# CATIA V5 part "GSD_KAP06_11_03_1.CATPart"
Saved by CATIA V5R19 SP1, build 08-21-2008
Part number: GSD_BLEND_04
Definition: Beispielmodell für die Funktion Übergang / Blend - Automatische Verbindung.
Description: CATIA V5 Flächenmodellierung  Copyright (c) 2009 Maik Hertha IT Consultants
Bounding box of the stored display mesh (mm): x -164.511 to 102.98, y -20 to 224.611, z -30.362 to 44.999
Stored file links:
  \GSD_BUCH_UEBUNG\GSD_KAP06_11_03_1.CATPart
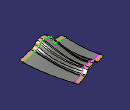
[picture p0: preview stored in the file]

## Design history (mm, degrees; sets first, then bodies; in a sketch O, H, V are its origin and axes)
AxisSystem1: origin (0, 0, 0), X (1, 0, 0), Y (0, 1, 0), Z (0, 0, 1)
Set1
  Sketch1 on ZX plane of AxisSystem1, origin (0, 0, 0), H (0, 0, 1), V (1, 0, 0)
    line L1 (-7.7811, 102.9804) -> (10.5771, 41.6998)
    arc A1 centre (44.1049, 51.744) radius 35 from (10.5771, 41.6998) to (24.809, 22.5435) ccw
    arc A2 centre (0, -15) radius 45 from (24.809, 22.5435) to (37.9923, 9.116) cw
    point P5 (0, -15)
    arc A3 centre (0, -15) radius 45 from (33.7014, -44.8197) to (4.0909, -59.8137) cw
    point P7 (0, -15)
    line L2 (-5, -69.7723) -> (-5, -121.1063)
    construction line L3 (70.2481, 0) -> (-64.8444, 0)
    point P8 (70.2481, 0)
    construction line L4 (0, 45.8622) -> (0, -41.9018)
    point P10 (0, 45.8622)
    curve C1
    arc A4 centre (5, -69.7723) radius 10 from (4.0909, -59.8137) to (-5, -69.7723) ccw
    arc A5 centre (0, -15) radius 45 from (37.9923, 9.116) to (43.6257, -3.9639) cw
    arc A6 centre (0, -15) radius 45 from (41.4452, -32.5298) to (33.7014, -44.8197) cw
    arc A7 centre (0, -15) radius 45 from (43.6257, -3.9639) to (41.4452, -32.5298) cw
    radius A3 = 45
    distance L4 L2 = 5
    distance P5 L3 = 15
    radius A4 = 10
    radius A1 = 35
    tangency: A1 L1, A2 A1, A3 A2, A4 L2, A4 A3
    vertical: L2 V, L4 V
    coincidence: P7 P5, P8 H, P10 V, P5 L4, A2 A5, A5 A6, A5 A7
    horizontal: L3 H
  Sketch2 on XY plane of AxisSystem1, origin (0, 0, 0), H (1, 0, 0), V (0, 1, 0)
    spline S1 through (63.5198, 0.6594) (52.4947, 108.5036) (27.7222, 201.6743)
    construction line L1 (63.5198, -33.9776) -> (63.5198, 23.4257)
    curve C1
    vertical: L1 V
  Plane1: type Normal, Curve Sketch2.C1, RefPoint {point type OnCurve, Support Sketch2.C1, Ratio 1}
  Sketch3 on Plane1, origin (27.7222, 201.6743, 0), H (-0.9497, -0.3131, 0), V (0, 0, 1)
    line L1 (-12.5925, -30.3622) -> (43.5645, -30.3622)
    line L2 (50.3453, -27.7121) -> (65.7944, -13.4594)
    line L3 (77.0077, -9.5205) -> (111.3244, -11.9105)
    line L4 (134.514, -21.3899) -> (139.6722, -25.7927)
    line L5 (149.4105, -29.3837) -> (195.8144, -29.3837)
    curve C1
    arc A1 centre (43.5645, -20.3622) radius 10 from (43.5645, -30.3622) to (50.3453, -27.7121) ccw
    arc A2 centre (75.9655, -24.4842) radius 15 from (65.7944, -13.4594) to (77.0077, -9.5205) cw
    arc A3 centre (108.5452, -51.8139) radius 40 from (111.3244, -11.9105) to (134.514, -21.3899) cw
    arc A4 centre (149.4105, -14.3837) radius 15 from (139.6722, -25.7927) to (149.4105, -29.3837) ccw
    radius A1 = 10
    radius A4 = 15
    radius A3 = 40
    radius A2 = 15
    horizontal: L1 H, L5 H
    tangency: A1 L1, A1 L2, A2 L2, A2 L3, A3 L3, A3 L4, A4 L4, A4 L5
  Extrude1: Lim1 20, Lim2 0, Element1 Sketch3.C1, Direction Plane1
  Extrude2: Lim1 20, Lim2 0, Element1 Sketch1.C1, Direction zx-plane
Set2
  Blend1: StartLimit {blendlimit Support Extrude2, Curve Sketch1.C1}, EndLimit {blendlimit Support Extrude1, Curve Sketch3.C1}
Body1 (main body)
